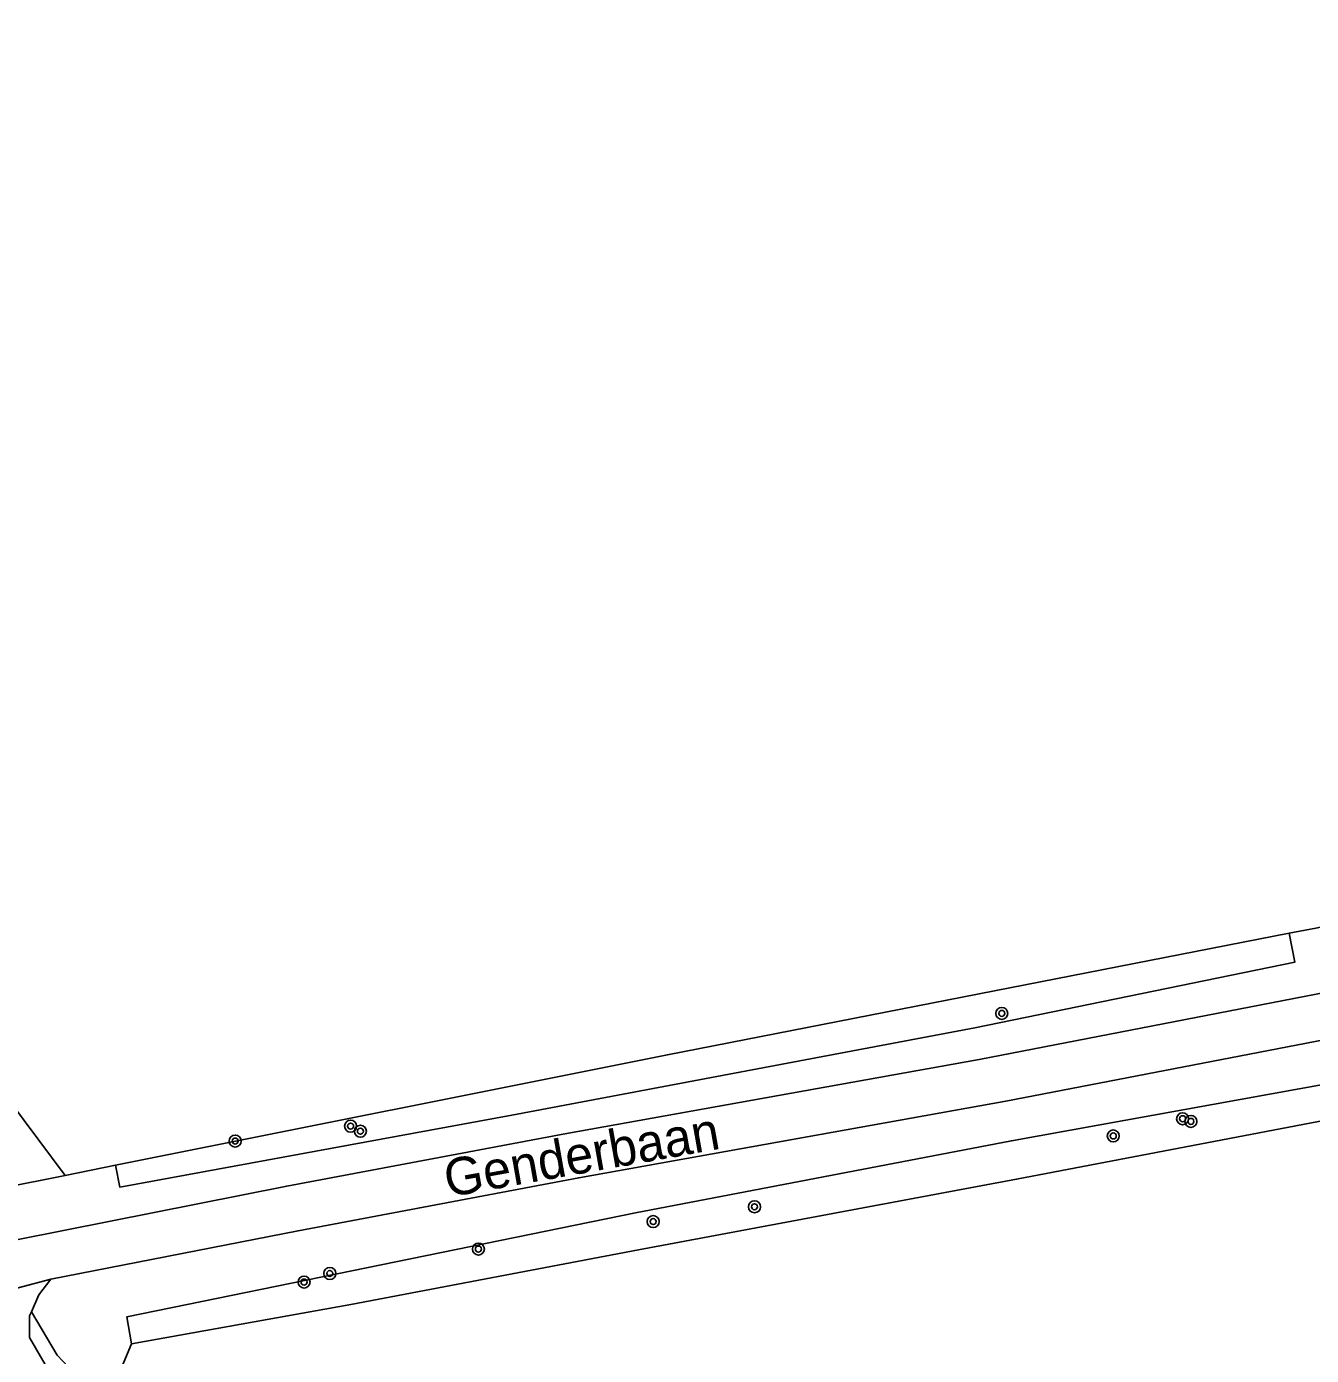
# Model space of a CAD drawing. Extents: x 126000 to 131009, y 393000 to 395500.
# Drawn here: x 129852.3 to 129938.2, y 394865.1 to 394953.9 of the extents above; entities that cross this region are included whole.
import ezdxf

# ---------------------------------------------------------------- set-up
doc = ezdxf.new("R2010")
doc.units = 0
for name, color, linetype in [('gg-afsc-draadraster', 7, 'Continuous'), ('gg-anno-openbare ruimte label', 7, 'Continuous'), ('gg-knt-verharding', 7, 'Continuous'), ('gg-kntw-greppel-droge sloot', 7, 'Continuous'), ('gt-grn-groengrens', 7, 'Continuous'), ('gt-grn-groengrens NZ', 7, 'Continuous'), ('gt-grn-vlakafsluiter', 7, 'Continuous'), ('gt-symb-boom', 7, 'Continuous')]:
    doc.layers.add(name, color=color, linetype=linetype)

# ---------------------------------------------------------------- blocks, each defined once
blk = doc.blocks.new('gt0-BOOM')
at = {"layer": 'gt-symb-boom'}
for radius in [0.4, 0.2]:
    blk.add_circle((0, 0), radius, dxfattribs=at)

msp = doc.modelspace()

# ---------------------------------------------------------------- linework, layer by layer
at = {"layer": 'gg-afsc-draadraster'}
msp.add_line((129858.276, 394877.821), (129854.916, 394877.148), dxfattribs=at)
for points in [[(129936.68, 394893.316), (129938.454, 394893.662), (129941.405, 394894.278)], [(129936.68, 394893.316), (129895.149, 394885.208), (129858.276, 394877.821)], [(129951.363, 394883.167), (129918.472, 394876.894), (129893.229, 394872.168), (129874.014, 394868.532), (129859.355, 394865.892)], [(129854.916, 394877.148), (129846.726, 394875.507), (129843.881, 394875.219)], [(129857.796, 394861.539), (129857.712, 394861.959), (129859.355, 394865.892)]]:
    msp.add_lwpolyline(points, dxfattribs=at)
at = {"layer": 'gg-knt-verharding'}
for points in [[(130276.779, 394953.879), (130194.556, 394937.025), (130118.723, 394921.903), (130095.926, 394917.085), (130053.967, 394908.73), (130023.35, 394902.489), (129976.539, 394893.418), (129942.804, 394886.944), (129917.763, 394882.112), (129889.227, 394876.991), (129870.482, 394873.444), (129853.964, 394870.212)], [(130185.427, 394938.52), (130095.342, 394920.228), (130053.803, 394911.932), (130022.868, 394905.707), (129976.149, 394896.552), (129915.977, 394884.892), (129888.306, 394879.915), (129869.728, 394876.435), (129842.902, 394871.111), (129841.273, 394870.591)], [(129853.964, 394870.212), (129853.167, 394869.179), (129852.668, 394868.041)], [(129852.668, 394868.041), (129852.549, 394867.77), (129852.533, 394866.309), (129853.593, 394864.524), (129865.726, 394851.707), (129890.083, 394825.876), (129907.16, 394807.685), (129925.237, 394788.466), (129936.89, 394776), (129959.084, 394752.224), (129976.505, 394733.597), (130000.008, 394708.71), (130012.983, 394694.731), (130030.308, 394676.235), (130051.582, 394653.058), (130074.322, 394629.354)]]:
    msp.add_lwpolyline(points, dxfattribs=at)
at = {"layer": 'gg-kntw-greppel-droge sloot'}
for points in [[(129858.276, 394877.821), (129858.567, 394876.368), (129884.755, 394881.174), (129915.691, 394887.007), (129937.058, 394891.378), (129936.68, 394893.316)], [(129859.355, 394865.892), (129859.033, 394867.689), (129893.028, 394874.642), (129918.13, 394879.463), (129950.768, 394885.363), (129951.363, 394883.167)]]:
    msp.add_lwpolyline(points, dxfattribs=at)
at = {"layer": 'gt-grn-groengrens'}
msp.add_line((129854.916, 394877.148), (129814.779, 394930.86), dxfattribs=at)
at = {"layer": 'gt-grn-groengrens NZ'}
msp.add_lwpolyline([(129852.668, 394868.041), (129854.396, 394865.13), (129857.796, 394861.539)], dxfattribs=at)
at = {"layer": 'gt-grn-vlakafsluiter'}
msp.add_line((129845.867, 394868.08), (129853.964, 394870.212), dxfattribs=at)

# ---------------------------------------------------------------- block references
at = {"layer": 'gt-symb-boom'}
for p in [(129917.485, 394887.966), (129929.562, 394880.933), (129873.989, 394880.435), (129874.643, 394880.097), (129930.117, 394880.756), (129866.278, 394879.439), (129924.933, 394879.78), (129900.967, 394875.05), (129894.199, 394874.062), (129882.526, 394872.226), (129872.601, 394870.594), (129870.88, 394870.022)]:
    msp.add_blockref('gt0-BOOM', p, dxfattribs=at)

# ---------------------------------------------------------------- texts
at = {"layer": 'gg-anno-openbare ruimte label'}
msp.add_text('Genderbaan', height=2.5, rotation=10.1, dxfattribs=at).set_placement((129880.48, 394875.678))

doc.saveas('drawing.dxf')
